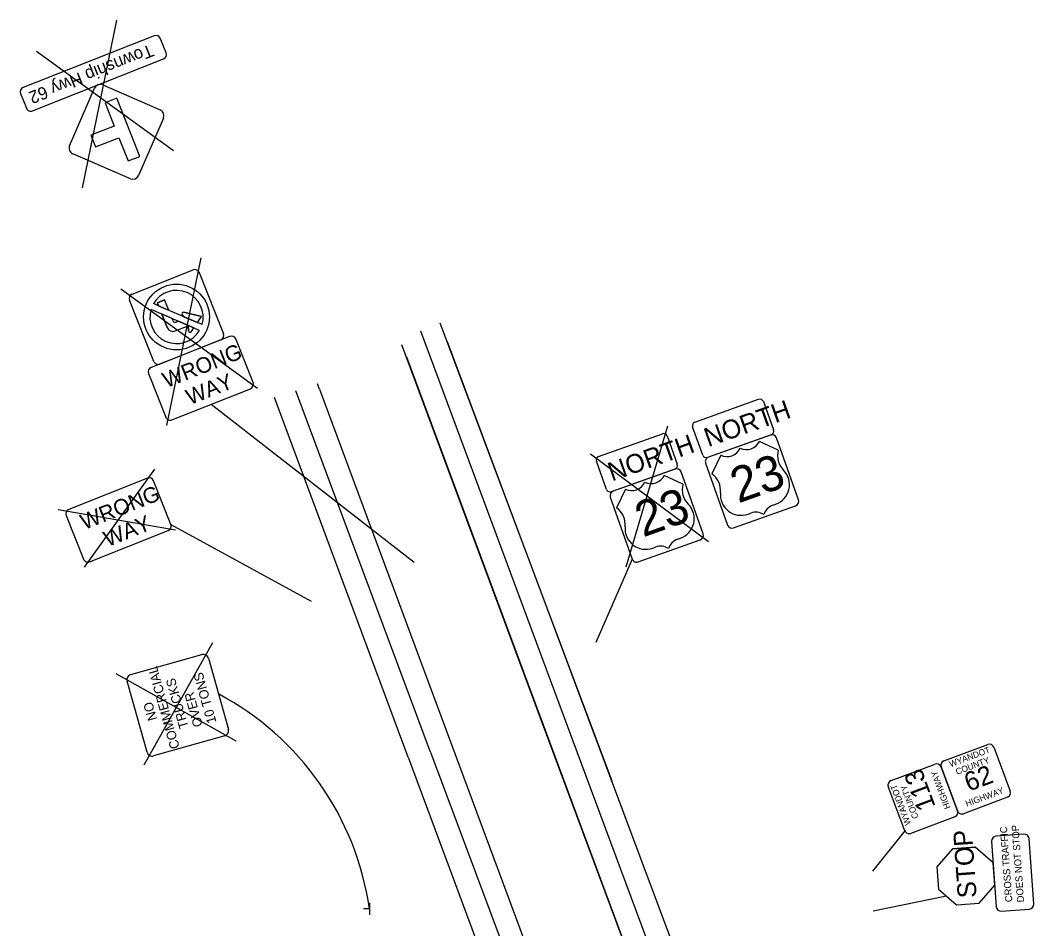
# Model space of a CAD drawing. Extents: x 179840 to 180553, y 300239 to 301090.
# Drawn here: x 179973 to 180513, y 300607 to 301090 of the extents above; entities that cross this region are included whole.
import ezdxf

# ---------------------------------------------------------------- set-up
doc = ezdxf.new("R2010")
doc.units = 0
for name, color, linetype in [('DR_P_Ditch', 7, 'Continuous'), ('MT_P_CL_40', 7, 'Continuous'), ('PM_P_Edge_Line', 7, 'Continuous'), ('PV_P_Saw_Cut_Line', 7, 'Continuous'), ('PV_X_Shoulder_Aggregate', 7, 'Continuous'), ('RW_P_Const_Limits', 7, 'Continuous')]:
    doc.layers.add(name, color=color, linetype=linetype)

msp = doc.modelspace()

# ---------------------------------------------------------------- linework, layer by layer
at = {"layer": 'DR_P_Ditch'}
for p, q in [((180288.27, 300685.29), (180196.73, 300929.22)), ((180248.33, 300723.77), (180176.3, 300917.65)), ((180132.45, 300894.04), (180131.29, 300896.92)), ((180179.58, 300698.16), (180108.39, 300889.69)), ((180407.15, 300297.25), (180248.33, 300723.77))]:
    msp.add_line(p, q, dxfattribs=at)
at = {"layer": 'MT_P_CL_40'}
for p, q in [((180276.74, 300681.88), (180186.34, 300924.85)), ((180191.6, 300700.84), (180119.87, 300893.19)), ((180346.46, 300494.63), (180276.74, 300681.88))]:
    msp.add_line(p, q, dxfattribs=at)
at = {"layer": 'PM_P_Edge_Line'}
for p, q in [((180200.42, 300919.36), (180340.54, 300544.7)), ((180178.69, 300911.24), (180318.13, 300536.33)), ((180132.45, 300894.04), (180271.8, 300519.09)), ((180179.58, 300698.16), (180249.31, 300510.72))]:
    msp.add_line(p, q, dxfattribs=at)
at = {"layer": 'PV_P_Saw_Cut_Line'}
for p, q in [((180006.3, 301001.2), (180024.54, 301090.43)), ((179981.82, 301073.99), (180054.66, 301021.13)), ((180024.47, 301048.97), (180018.27, 301046.51)), ((180018.27, 301046.51), (180023.18, 301034.11)), ((180036.74, 301017.98), (180024.47, 301048.97)), ((180023.18, 301034.11), (180010.78, 301029.2)), ((180010.78, 301029.2), (180013.24, 301023.01)), ((180013.24, 301023.01), (180025.63, 301027.92)), ((180025.63, 301027.92), (180030.54, 301015.52)), ((180030.54, 301015.52), (180036.74, 301017.98)), ((180051.12, 300874.72), (180069.37, 300963.96)), ((180026.64, 300947.51), (180099.48, 300894.65)), ((180332.27, 300876.55), (180366.18, 300888.64)), ((180368.73, 300887.42), (180374.11, 300872.35)), ((180295.69, 300799.47), (180317.8, 300874.52)), ((180336.43, 300858.92), (180331.06, 300873.99)), ((180372.9, 300869.8), (180338.99, 300857.71)), ((180376.64, 300861.51), (180366.66, 300866.25)), ((180276.66, 300859.65), (180339.44, 300812.96)), ((180346.06, 300858.9), (180341.32, 300848.92)), ((180007.37, 300799.2), (180044.84, 300851.54)), ((179993.36, 300829.9), (180055.73, 300819.14)), ((180373.79, 300832.29), (180375.26, 300832.82)), ((180360.54, 300827.57), (180362.02, 300828.1)), ((180039.18, 300694.12), (180075.71, 300759.17)), ((180023.96, 300742.68), (180087.85, 300706.8))]:
    msp.add_line(p, q, dxfattribs=at)
for points in [[(180017.05, 301055.99), (180047.64, 301042.76)], [(179999.43, 301023.66), (180012.67, 301054.25)], [(180049.38, 301038.37), (180036.15, 301007.78)], [(180031.76, 301006.04), (180001.17, 301019.28)], [(180372.42, 300869.63), (180339.46, 300857.88)], [(180387.37, 300835.15), (180375.62, 300868.11)], [(180337.94, 300854.68), (180349.69, 300821.71)], [(180352.89, 300820.2), (180385.86, 300831.95)]]:
    msp.add_lwpolyline(points, dxfattribs=at)
for centre, radius, start, end in [((180015.73, 301052.93), 3.33, 66.6096, 156.6096), ((180046.32, 301039.7), 3.33, 336.6096, 66.6096), ((180002.49, 301022.33), 3.33, 156.6096, 246.6096), ((180033.09, 301009.1), 3.33, 246.6096, 336.6096), ((180366.85, 300886.75), 2, 19.6201, 109.6201), ((180332.94, 300874.66), 2, 109.6201, 199.6201), ((180372.22, 300871.68), 2, 289.6201, 19.6201), ((180373.26, 300867.27), 2.5, 19.6201, 109.6201), ((180349.34, 300865.99), 7.81, 245.1931, 334.0471), ((180359.64, 300869.67), 7.81, 245.1931, 334.0471), ((180387.19, 300858.61), 10.94, 164.6192, 225.073), ((180338.31, 300859.59), 2, 199.6201, 289.6201), ((180340.3, 300855.52), 2.5, 109.6201, 199.6201), ((180371.7, 300843.16), 10.94, 288.9818, 44.7882), ((180334.99, 300840), 10.94, 354.1672, 54.621), ((180356.76, 300837.83), 10.94, 174.452, 290.2584), ((180385.02, 300834.31), 2.5, 289.6201, 19.6201), ((180376.41, 300824.94), 7.81, 109.6201, 162.7502), ((180364.64, 300820.74), 7.81, 56.49, 109.6201), ((180352.05, 300822.55), 2.5, 199.6201, 289.6201)]:
    msp.add_arc(centre, radius, start, end, dxfattribs=at)
at = {"layer": 'PV_X_Shoulder_Aggregate'}
msp.add_line((180191.6, 300700.84), (180261.02, 300514.81), dxfattribs=at)
at = {"layer": 'RW_P_Const_Limits'}
for p, q in [((180046.13, 300940.09), (180050, 300941.62)), ((180050, 300941.62), (180046.13, 300940.09)), ((180046.79, 300938.41), (180046.13, 300940.09)), ((180046.13, 300940.09), (180046.79, 300938.41)), ((180046.79, 300938.41), (180050, 300937.02)), ((180052.2, 300936.07), (180050, 300941.62)), ((180052.2, 300936.07), (180050, 300941.62)), ((180050, 300937.02), (180052.2, 300936.07)), ((180068.57, 300925.36), (180042.74, 300936.53)), ((180051.34, 300926.92), (180048.53, 300934.02)), ((180048.68, 300933.96), (180048.53, 300934.02)), ((180048.53, 300934.02), (180051.34, 300926.92)), ((180053.94, 300931.68), (180048.68, 300933.96)), ((180054.47, 300930.34), (180053.94, 300931.68)), ((180054.47, 300930.34), (180053.94, 300931.68)), ((180059.37, 300933.64), (180060.18, 300932.64)), ((180059.37, 300933.64), (180060.18, 300932.64)), ((180060.17, 300932.62), (180067.4, 300929.5)), ((180060.2, 300934.97), (180069.62, 300932.81)), ((180069.62, 300932.81), (180060.2, 300934.97)), ((180067.4, 300929.5), (180069.62, 300932.81)), ((180067.4, 300929.5), (180069.62, 300932.81)), ((180055.67, 300925.05), (180062.52, 300927.76)), ((180055.67, 300925.05), (180062.52, 300927.76)), ((180056.03, 300929.67), (180057.37, 300930.2)), ((180057.37, 300930.2), (180056.03, 300929.67)), ((180065.51, 300926.68), (180057.37, 300930.2)), ((180062.71, 300925.19), (180062.52, 300927.76)), ((180062.52, 300927.76), (180062.71, 300925.19)), ((180064.24, 300924.79), (180065.51, 300926.68)), ((180064.24, 300924.79), (180065.51, 300926.68)), ((180074.73, 300885.99), (180182.79, 300802)), ((180281.02, 300858.28), (180314.94, 300870.35)), ((180317.5, 300869.13), (180322.86, 300854.06)), ((180285.18, 300840.65), (180279.81, 300855.72)), ((180321.65, 300851.5), (180287.73, 300839.43)), ((180325.92, 300843.41), (180315.94, 300848.15)), ((180295.33, 300840.81), (180290.59, 300830.83)), ((180053.3, 300822), (180127.95, 300781.19)), ((180323.05, 300814.19), (180324.52, 300814.71)), ((180309.8, 300809.48), (180311.27, 300810)), ((180298.95, 300803.62), (180279.49, 300759.18)), ((180464.78, 300696.14), (180488.2, 300704.88)), ((180491.42, 300703.41), (180500.16, 300679.99)), ((180436.67, 300685.65), (180460.1, 300694.39)), ((180472.05, 300669.5), (180463.31, 300692.93)), ((180463.31, 300692.93), (180472.05, 300669.5)), ((180443.94, 300659.01), (180435.2, 300682.44)), ((180498.69, 300676.77), (180475.27, 300668.03)), ((180470.58, 300666.29), (180447.16, 300657.55)), ((180443.94, 300659.01), (180426.76, 300637.44)), ((180469.4, 300649.39), (180461.07, 300639.77)), ((180469.4, 300649.39), (180481.37, 300650.25)), ((180481.37, 300650.25), (180469.4, 300649.39)), ((180481.37, 300650.25), (180469.4, 300649.39)), ((180490.99, 300641.92), (180481.37, 300650.25)), ((180491.85, 300629.95), (180490.99, 300641.92)), ((180461.07, 300639.77), (180461.93, 300627.8)), ((180483.52, 300620.33), (180491.85, 300629.95)), ((180466.17, 300624.13), (180427.15, 300616.19)), ((180461.93, 300627.8), (180471.55, 300619.47)), ((180158.96, 300620.63), (180159, 300614.23)), ((180471.55, 300619.47), (180483.52, 300620.33)), ((180158.98, 300617.43), (180155.78, 300617.41))]:
    msp.add_line(p, q, dxfattribs=at)
for points in [[(180044.45, 301082.23), (179974.72, 301054.61)], [(180050.77, 301073.08), (180047.7, 301080.83)], [(179979.63, 301042.22), (180049.36, 301069.84)], [(179973.32, 301051.37), (179976.39, 301043.62)], [(180032.68, 300944.62), (180065.22, 300957.51)], [(180068.46, 300956.11), (180081.35, 300923.57)], [(180044.17, 300908.84), (180031.28, 300941.38)], [(180050, 300937.02), (180044.06, 300939.59)], [(180069.89, 300928.42), (180055.26, 300934.74), (180050, 300937.02)], [(180060.18, 300932.64), (180060.17, 300932.62)], [(180084.6, 300922.16), (180042.76, 300905.59)], [(180079.95, 300920.32), (180047.41, 300907.43)], [(180097.05, 300897.52), (180087.84, 300920.76)], [(180041.36, 300902.35), (180050.57, 300879.1)], [(180053.81, 300877.7), (180095.65, 300894.27)], [(180321.7, 300851.53), (180288.73, 300839.79)], [(180040.85, 300846.65), (179999.01, 300830.07)], [(180336.63, 300817.03), (180324.9, 300850.01)], [(180053.3, 300822), (180044.09, 300845.24)], [(180287.21, 300836.6), (180298.95, 300803.62)], [(179997.61, 300826.83), (180006.82, 300803.59)], [(180010.06, 300802.18), (180051.9, 300818.76)], [(180302.14, 300802.11), (180335.11, 300813.84)], [(180031.92, 300742.12), (180069.83, 300752.76)], [(180073.29, 300750.81), (180083.94, 300712.9)], [(180040.61, 300700.74), (180029.97, 300738.65)], [(180081.99, 300709.43), (180044.08, 300698.79)], [(180507.45, 300657.14), (180492.49, 300656.06)], [(180490.17, 300653.39), (180492.68, 300618.48)], [(180512.63, 300619.91), (180510.12, 300654.82)], [(180495.35, 300616.16), (180510.31, 300617.24)]]:
    msp.add_lwpolyline(points, dxfattribs=at)
msp.add_circle((180056.32, 300932.47), 17.5, dxfattribs=at)
for centre, radius, start, end in [((180045.37, 301079.91), 2.5, 21.6096, 111.6096), ((180048.44, 301072.16), 2.5, 291.6096, 21.6096), ((179975.64, 301052.29), 2.5, 111.6096, 201.6096), ((179978.71, 301044.54), 2.5, 201.6096, 291.6096), ((180066.14, 300955.19), 2.5, 21.6096, 111.6096), ((180033.6, 300942.3), 2.5, 111.6096, 201.6096), ((180056.32, 300932.47), 14.17, 343.3659, 149.8533), ((180056.32, 300932.47), 14.17, 343.3659, 149.8533), ((180056.32, 300932.47), 14.17, 163.3659, 329.8533), ((180060.01, 300934.16), 0.833, 77.0933, 218.9714), ((180060.01, 300934.16), 0.833, 77.0933, 218.9714), ((180054.44, 300928.15), 3.33, 201.6096, 291.6096), ((180054.44, 300928.15), 3.33, 201.6096, 291.6096), ((180055.59, 300930.78), 1.2, 201.6096, 291.6096), ((180055.59, 300930.78), 1.2, 201.6096, 291.6096), ((180063.54, 300925.25), 0.833, 184.2478, 326.1259), ((180063.54, 300925.25), 0.833, 184.2478, 326.1259), ((180079.03, 300922.65), 2.5, 291.6096, 21.6096), ((180085.52, 300919.84), 2.5, 21.6096, 111.6096), ((180043.68, 300903.27), 2.5, 111.6096, 201.6096), ((180046.49, 300909.76), 2.5, 201.6096, 291.6096), ((180094.73, 300896.6), 2.5, 291.6096, 21.6096), ((180052.89, 300880.02), 2.5, 201.6096, 291.6096), ((180315.61, 300868.46), 2, 19.5895, 109.5895), ((180281.7, 300856.39), 2, 109.5895, 199.5895), ((180320.98, 300853.39), 2, 289.5895, 19.5895), ((180322.54, 300849.17), 2.5, 19.5895, 109.5895), ((180041.77, 300844.32), 2.5, 21.6096, 111.6096), ((180308.92, 300851.57), 7.81, 245.1625, 334.0165), ((180287.06, 300841.32), 2, 199.5895, 289.5895), ((180298.61, 300847.9), 7.81, 245.1625, 334.0165), ((180336.46, 300840.5), 10.94, 164.5885, 225.0424), ((180289.57, 300837.44), 2.5, 109.5895, 199.5895), ((179999.93, 300827.75), 2.5, 111.6096, 201.6096), ((180284.25, 300821.92), 10.94, 354.1366, 54.5904), ((180320.97, 300825.06), 10.94, 288.9512, 44.7576), ((180050.98, 300821.08), 2.5, 291.6096, 21.6096), ((180306.02, 300819.74), 10.94, 174.4214, 290.2277), ((180325.67, 300806.83), 7.81, 109.5895, 162.7196), ((180334.28, 300816.2), 2.5, 289.5895, 19.5895), ((180313.89, 300802.64), 7.81, 56.4594, 109.5895), ((180009.14, 300804.51), 2.5, 201.6096, 291.6096), ((180301.3, 300804.46), 2.5, 199.5895, 289.5895), ((180070.59, 300750.05), 2.81, 15.6794, 105.6794), ((180032.68, 300739.41), 2.81, 105.6794, 195.6794), ((180005.83, 300595.3), 154.75, 8.2225, 61.9409), ((180081.23, 300712.14), 2.81, 285.6794, 15.6794), ((180489.08, 300702.54), 2.5, 20.4629, 110.4629), ((180043.32, 300701.5), 2.81, 195.6794, 285.6794), ((180460.97, 300692.05), 2.5, 20.4629, 110.4629), ((180465.65, 300693.8), 2.5, 110.4629, 200.4629), ((180437.55, 300683.31), 2.5, 110.4629, 200.4629), ((180497.82, 300679.12), 2.5, 290.4629, 20.4629), ((180469.71, 300668.63), 2.5, 290.4629, 20.4629), ((180474.39, 300670.38), 2.5, 200.4629, 290.4629), ((180446.29, 300659.89), 2.5, 200.4629, 290.4629), ((180507.63, 300654.64), 2.5, 4.1044, 94.1044), ((180492.67, 300653.57), 2.5, 94.1044, 184.1044), ((180510.13, 300619.73), 2.5, 274.1044, 4.1044), ((180495.17, 300618.66), 2.5, 184.1044, 274.1044)]:
    msp.add_arc(centre, radius, start, end, dxfattribs=at)

# ---------------------------------------------------------------- texts
at = {"layer": 'PV_P_Saw_Cut_Line'}
for s, height, p in [('NORTH', 10, (180339.36, 300863.15)), ('23', 18.75, (180355.36, 300833.19))]:
    msp.add_text(s, height=height, rotation=19.6201, dxfattribs=at).set_placement(p)
at = {"layer": 'RW_P_Const_Limits'}
for s, height, rotation, p in [('Township Hwy 62', 6.666, 201.6096, (180042.44, 301077.85)), ('WRONG', 8.375, 21.6096, (180050.97, 300894.57)), ('WAY', 8.375, 21.6096, (180063.42, 300885.52)), ('NORTH', 10, 19.5895, (180288.11, 300844.88)), ('WRONG', 8.375, 21.6096, (180007.22, 300819.06)), ('23', 18.75, 19.5895, (180304.62, 300815.09)), ('WAY', 8.375, 21.6096, (180019.67, 300810.01)), ('COMMERCIAL', 5, 105.6794, (180058.06, 300703.31)), ('10 TONS', 5, 105.6794, (180077.63, 300716.86)), ('TRUCKS', 5, 105.6794, (180062.81, 300714.17)), ('   OVER', 5, 105.6794, (180071.87, 300709.64)), ('NO', 5, 105.6794, (180046.06, 300718.32)), ('WYANDOT', 3.333, 20.4629, (180468.42, 300692.73)), ('COUNTY', 3.333, 20.4629, (180471.8, 300688.69)), ('113', 10, 110.4629, (180460.49, 300671.87)), ('HIGHWAY', 3.333, 110.4629, (180468.4, 300671.24)), ('62', 10, 20.4629, (180477.96, 300679.71)), ('WYANDOT', 3.333, 110.4629, (180447.36, 300662.65)), ('COUNTY', 3.333, 110.4629, (180451.39, 300666.04)), ('HIGHWAY', 3.333, 20.4629, (180477.01, 300671.69)), ('STOP', 10, 94.1044, (180482.29, 300623.5)), ('CROSS TRAFFIC', 3.75, 94.1044, (180501.26, 300621.11)), ('DOES NOT STOP', 3.75, 94.1044, (180507.53, 300621))]:
    msp.add_text(s, height=height, rotation=rotation, dxfattribs=at).set_placement(p)

doc.saveas('drawing.dxf')
